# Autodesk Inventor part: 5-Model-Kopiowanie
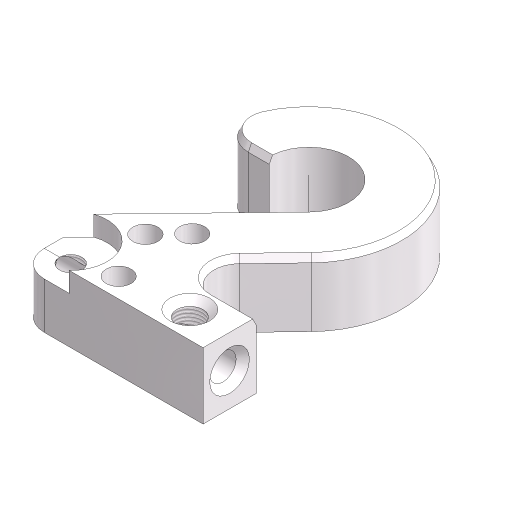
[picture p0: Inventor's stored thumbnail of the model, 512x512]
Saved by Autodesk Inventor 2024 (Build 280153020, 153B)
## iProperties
Company: ATC
Shininess: 21.0
Length Units: 11269
Angle Units: 11279
Time Units: 11290
Mass Units: 11283
Compacted: True
Created: 2023-03
Part Number: 5-Model-Kopiowanie
Document SubType Name: Modeling
Designer: Andrzej Jaskulski
Material: Kurs-AJ
Density: 1 g/cm^3
Appearance: Kurs-AJ
Checked By: A.J.
Engr Approved By: Andrzej Jaskulski
Mfg Approved By: Andrzej Jaskulski
Authority: A.J.
Density: 0.0
Volumn: 0.0
Area: 0.0
PropertySet Name: Model Information
Control State: 0
Master: False
Checked Out: False
Title: A.J.: Kurs R2024-MEP
Author: Andrzej Jaskulski
Revision Number: 1/24
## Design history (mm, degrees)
sketch "Zarys dwójki"
  geometry: L1 (140, 0.063)-(0, 0.063) reference; L2 (0, 0.063)-(0, 34.389) reference; L3 (0, 150.063)-(40, 150.063); L4 (140, 0.063)-(140, 40.063); L5 (140, 40.063)-(61.086, 40.063); L6 (61.086, 40.063)-(120.354, 101.437); L7 (91.58, 129.223)-(0, 34.389); A1 r 30 centre (70, 150.063) between (91.58, 129.223) and (40, 150.063); A2 r 70 centre (70, 150.063) between (120.354, 101.437) and (0, 150.063)
  constraints: 14 end point, 4 perpendicular, 4 point on circle, 2 centre point, 2 parallel, 2 tangent, 1 coincident
  dimensions: "d0" = 140 distance of L1.start L1.end; "d1" = 150 vertical distance of A1.centre L1.end; "d2" = 70 horizontal distance of L1.end A1.centre; "d3" = 46 deg angle of L6 L5; "d4" = 150 distance of L3.start L1.end (= d1); "d5" = 30 radius of A1; "d6" = 70 radius of A2
extrude "Dwójka" new body sketch "Zarys dwójki" distance "d7" = 50; taper "d8" = 0 deg
node "Oś walca"
fillet "Trzy Zaokrąglenia" dims "d12" = 20
chamfer "Faza 2,5x5" distance "d13" = 2.5; stored, may be unused: second distance "d14" = 5, angle "d15" = 45 deg
sketch "Szkic2"
  geometry: A1 r 20 centre (20, 20.063) between (0, 20.063) and (20, 0.063) reference; 2 further points
  constraints: 1 coincident
hole "Otwór W" sketch "Szkic2" diameter "d20" = 17; stored, may be unused: countersink angle "d24" = 90 deg, drill point angle "d26" = 118 deg; dims "d21" = 42, "d22" = 55, "d23" = 15, "d25" = 45
sketch "Otw."
  geometry: L1 (140, 0.063)-(38.875, 0.063) reference; L2 (140, 37.563)-(140, 0.063) reference; 2 further points
  dimensions: "d27" = 20 distance from line of L1 point (110, 20.063); "d28" = 30 distance from line of L2 point (110, 20.063)
hole "Otwór-Ze Szkicu" sketch "Otw." at (110, 20.063) diameter "d29" = 20; stored, may be unused: countersink angle "d33" = 90 deg, drill point angle "d35" = 0 deg; dims "d30" = 42, "d31" = 30, "d32" = 15, "d34" = 45
feature "Gwint w Otwór-Ze Szkicu" dims "d57" = 10, "d58" = 0
sketch "Szkic4"
  geometry: L1 (0, 0)-(-50, 0) reference; L2 (0, 40)-(0, 0) reference; 2 further points
  dimensions: "d36" = 20 distance from line of L1 point (-25, 20) (= d27); "d37" = 25 distance from line of L2 point (-25, 20) (= 0.5 x d7)
hole "Otwór poziomy" sketch "Szkic4" diameter "d38" = 20; stored, may be unused: countersink angle "d42" = 90 deg, drill point angle "d44" = 0 deg; dims "d39" = 42, "d40" = 30, "d41" = 15, "d43" = 45
sketch "Otw. 4"
  geometry: L1 (40, 5.259)-(65, 5.259); L2 (65, 5.259)-(25, -33.368); L3 (68.972, -100.214)-(-1.275, -27.47) reference; C1 r 10 at (62.519, -64.741) reference; A1 r 27.5 centre (0, 0) between (-1.275, -27.47) and (12.802, 24.339) reference; 2 further points
  constraints: 4 end point, 1 coincident, 1 horizontal, 1 perpendicular
  dimensions: "d45" = 25 distance of L1.end L1.start; "d47" = 65 horizontal distance of L1.end A1.centre; "d48" = 70 vertical distance of C1.centre L1.end; "d49" = 40 horizontal distance of L1.end point (25, -33.368)
hole "Trzy Otwory" sketch "Otw. 4" at (40, 5.259), (65, 5.259), (25, -33.368) diameter "d50" = 19; stored, may be unused: countersink angle "d54" = 90 deg, drill point angle "d56" = 118 deg; dims "d51" = 6, "d52" = 40, "d53" = 12, "d55" = 8
node "Bryła1"
node "Korpusy bryłowe"
node "Korpusy powierzchniowe"
node "Początek"
node "Płaszczyzna YZ"
node "Płaszczyzna XZ"
node "Płaszczyzna XY"
node "Oś X"
node "Oś Y"
node "Oś Z"
node "Punkt środkowy"
other parameters: "d9" = 90 deg
